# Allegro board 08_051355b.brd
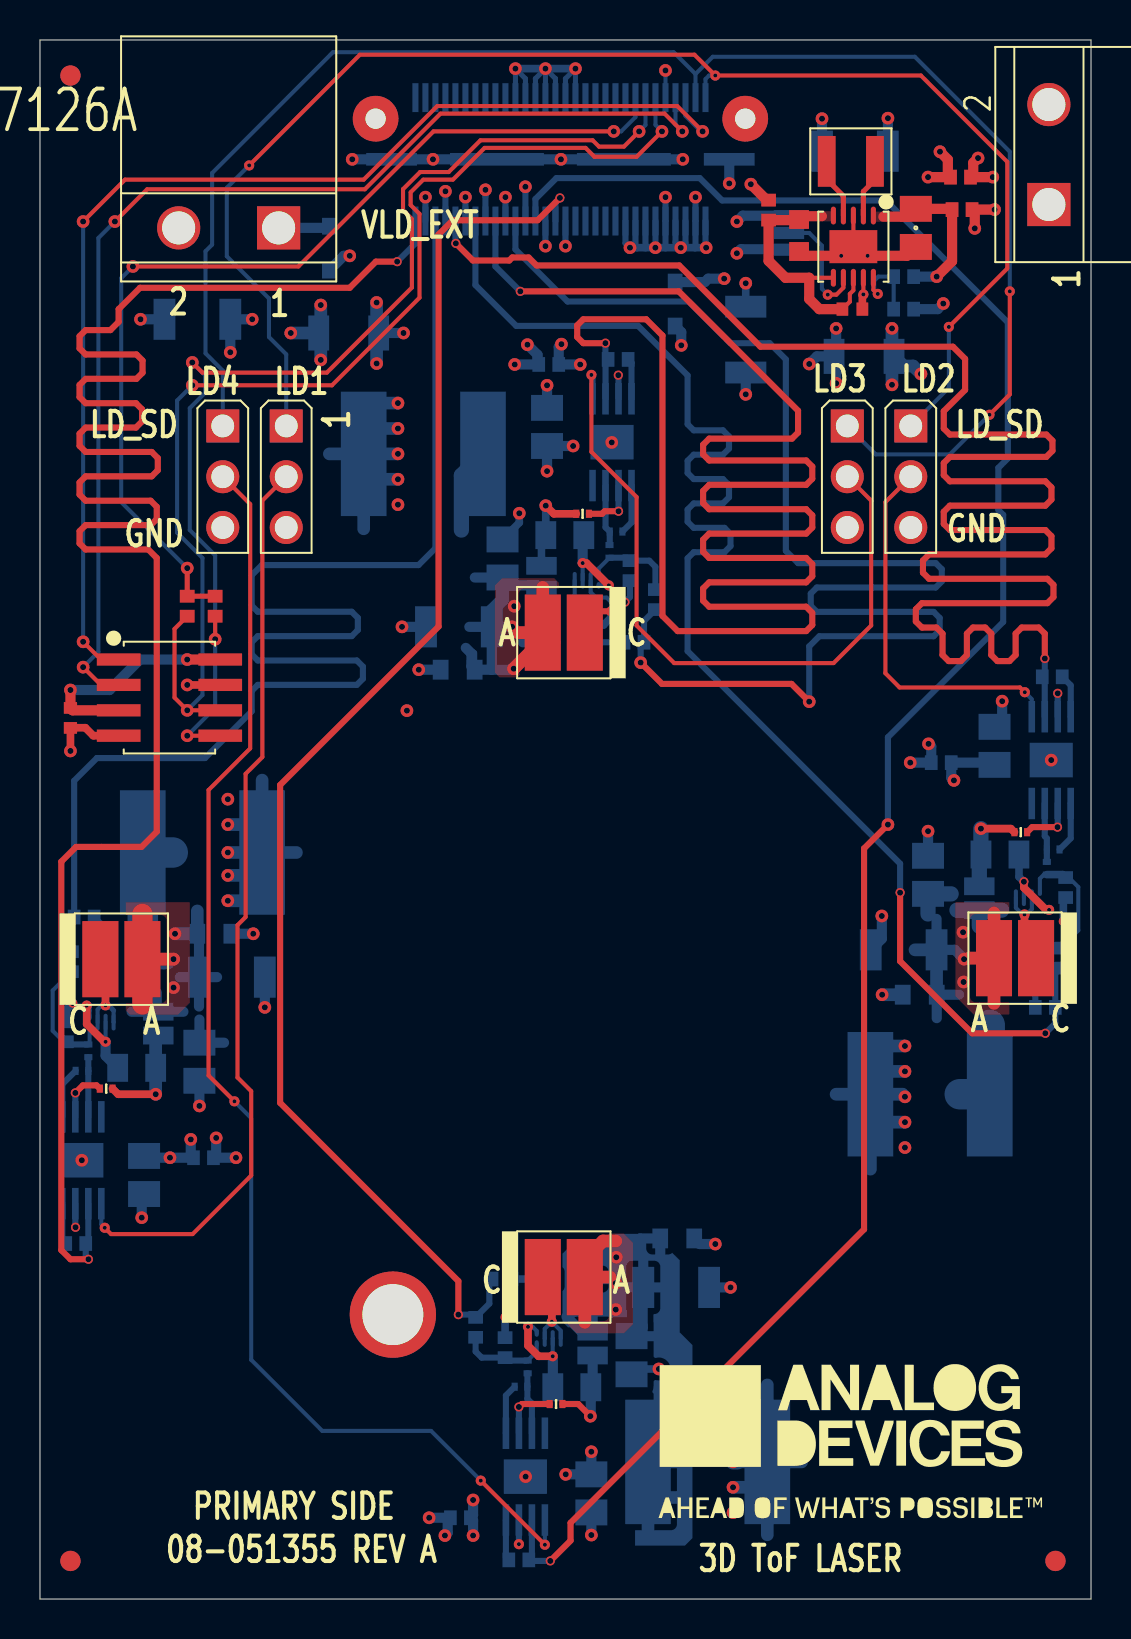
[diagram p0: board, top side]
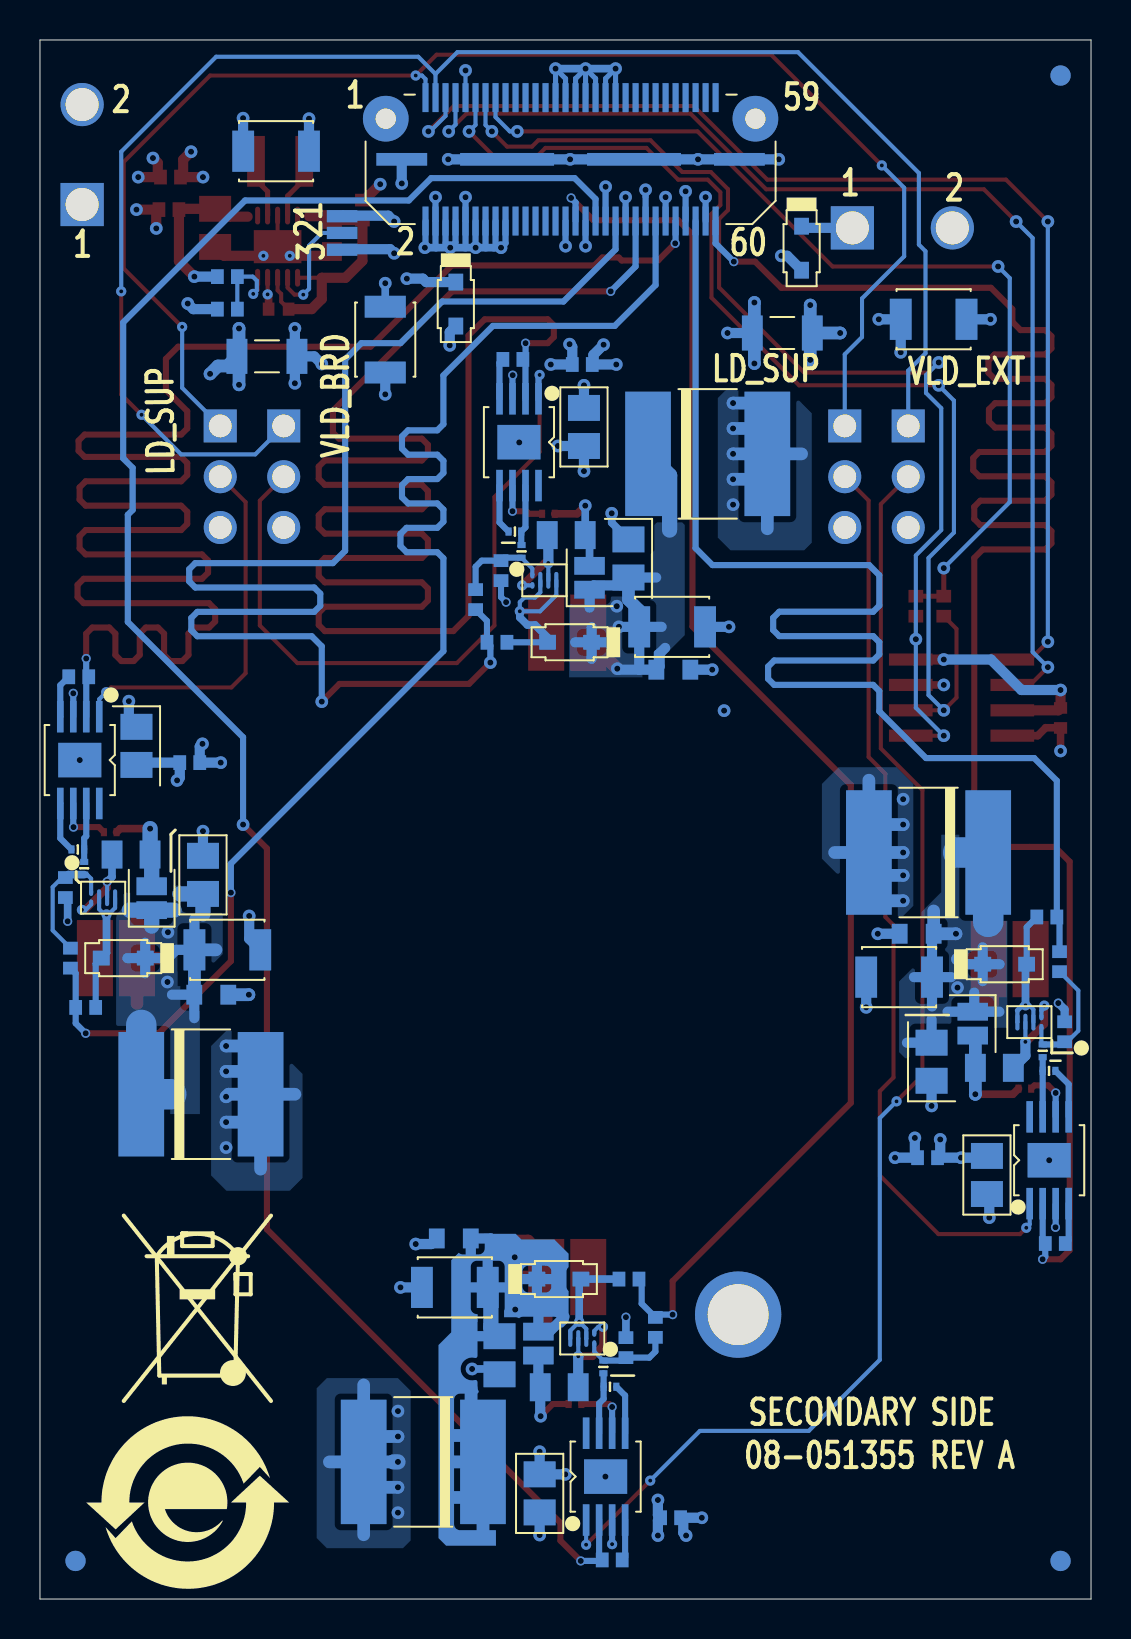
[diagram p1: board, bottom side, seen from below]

Outline 52.58 x 77.98 mm; copper layers: TOP, L2_GND, L3_PWR, L4_PWR, L5_GND, BOTTOM. Coordinates in mm from the lower left corner of the outline.
Outline path: 0,77.98 52.58,77.98 52.58,0 0,0 0,77.98

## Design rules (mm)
constraint set DEFAULT: min track width 0.203
net group TAL: nets TAL1 TAL2 TAL3 TAL4

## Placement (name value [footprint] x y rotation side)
C1  0.1uF  [C0201]  3.31 25.53 180 top
C2  0.1uF  [C0201]  25.82 9.75 180 top
C3  4.7UF  [C0805H53]  5.21 21.21 90 bottom
C4  4.7UF  [C0805H53]  27.58 5.28 90 bottom
C5  22NF  [C0306]  5.92 28.78 90 bottom
C6  22NF  [C0306]  27.65 12.78 90 bottom
C7  0.1uF  [C0201]  27.14 54.28 0 top
C8  0.1uF  [C0201]  49.06 38.35 0 top
C9  22UF  [C1210H106]  9.6 31.1 180 bottom
C10  22UF  [C1210H106]  31.83 15.59 180 bottom
C11  4.7UF  [C0805H53]  25.37 58.62 270 bottom
C12  4.7UF  [C0805H53]  47.75 42.67 270 bottom
C13  22UF  [C1210H106]  20.96 48.62 0 bottom
C14  22NF  [C0306]  25.09 51.08 270 bottom
C15  22UF  [C1210H106]  43.21 32.47 0 bottom
C16  22NF  [C0306]  46.99 35.05 270 bottom
C17  22UF  [C1210H106]  7.87 64.01 0 bottom
C18  22UF  [C1210H106]  35.31 62.99 90 bottom
C19  22UF  [C1210H106]  40.77 72.42 180 bottom
C20  470UF  [C7260]  8.13 37.34 0 bottom
C21  470UF  [C7260]  44.53 25.25 180 bottom
C22  470UF  [C7260]  33.4 6.86 0 bottom
C23  470UF  [C7260]  19.18 57.28 180 bottom
C24  10uF  [C0603]  37.97 68.2 90 top
C25  0.1UF  [C0402]  40.64 64.52 0 top
C26  22UF  [C0805H60]  43.81 68.58 90 top
C27  4.7UF  [C0805H53]  7.98 26.87 90 bottom
C28  4.7UF  [C0805H53]  44.42 36.22 270 bottom
C29  4.7UF  [C0805H53]  29.59 12.19 90 bottom
C30  4.7UF  [C0805H53]  23.14 52.04 270 bottom
C31  0.1UF  [C0402]  1.52 44.07 90 top
D5  PLZ13B-G3/H  [DO219AC]  4.32 31.75 180 bottom
D6  PLZ13B-G3/H  [DO219AC]  26.62 16 180 bottom
D7  PLZ13B-G3/H  [DO219AC]  14.48 67.56 270 bottom
D8  PLZ13B-G3/H  [DO219AC]  31.78 64.77 270 bottom
D9  PLZ13B-G3/H  [DO219AC]  26.09 47.85 0 bottom
D10  PLZ13B-G3/H  [DO219AC]  48.41 32.05 0 bottom
JP5  3PIN_SOLDER_JUMPER  [JPRSLD03]  37.47 68.33 270 bottom
L1  1.5UH  [L1008_A]  40.56 71.91 0 top
LD1  I940-G2332-NBC-D1-60B45R  [VCSEL2_3_5X3_5]  4.07 32 0 top
LD2  I940-G2332-NBC-D1-60B45R  [VCSEL2_3_5X3_5]  48.78 32.05 180 top
LD3  I940-G2332-NBC-D1-60B45R  [VCSEL2_3_5X3_5]  26.2 48.34 180 top
LD4  I940-G2332-NBC-D1-60B45R  [VCSEL2_3_5X3_5]  26.2 16.1 0 top
NOREF  -  []  -53.14 168.62 0 top
NOREF#2  -  [unnamed#2]  17.65 14.22 0 top
NOREF#3  -  []  1.52 1.91 0 top
NOREF#4  -  [unnamed#2]  50.8 1.91 0 top
NOREF#5  -  []  52.58 0 0 top
NOREF#6  -  []  1.52 1.91 0 top
NOREF#7  -  []  0 0 0 top
NOREF#8  -  [unnamed#2]  1.52 76.2 0 top
NOREF#9  -  []  52.58 0 90 top
NOREF#10  -  []  0 77.98 0 top
NOREF#11  -  [unnamed#2]  1.52 1.91 0 top
NOREF#12  -  []  40.56 7.87 0 top
NOREF#13  -  []  0 0 0 top
NOREF#14  -  []  -53.08 170.04 0 top
NOREF#15  -  []  52.58 0 90 top
NOREF#16  -  []  -34.29 -74.04 0 top
NOREF#17  -  []  0 77.98 270 top
NOREF#18  -  []  0 0 0 top
NOREF#19  -  []  -152.4 -254 0 top
NOREF#20  -  []  52.7 77.98 180 top
NOREF#21  -  []  26.57 98.68 0 top
NOREF#22  -  []  226.11 -117.6 0 top
NOREF#23  -  []  0 77.98 0 top
NOREF#24  -  []  119.38 127 0 top
NOREF#25  -  []  -57.86 157.56 0 top
NOREF#26  -  []  215.9 215.9 0 top
NOREF#27  -  []  -170.05 -267.97 0 top
NOREF#28  -  []  17.6 42.14 0 top
NOREF#29  -  []  45.19 4.83 180 bottom
NOREF#30  -  [unnamed#2]  1.52 76.2 180 bottom
NOREF#31  -  [unnamed#2]  1.52 1.91 180 bottom
NOREF#32  -  []  35.43 22.86 180 bottom
NOREF#33  -  [unnamed#2]  50.8 1.91 180 bottom
P1  QTH-030-04-L-D-A  [CNHDR2X30H630]  26.04 72.01 180 bottom
P2  Z5.530.3225.0  [CNWIELAND3225]  11.94 68.58 180 top
P3  22-03-2031  [CNMOLEX22-03-2031]  12.32 58.67 270 top
P4  22-03-2031  [CNMOLEX22-03-2031]  9.14 58.67 270 top
P5  22-03-2031  [CNMOLEX22-03-2031]  40.39 58.67 270 top
P6  22-03-2031  [CNMOLEX22-03-2031]  43.56 58.67 270 top
P7  Z5.530.3225.0  [CNWIELAND3225]  50.47 69.75 90 top
Q1  EPC2014C  [EPCX014X]  3.08 28.85 90 bottom
Q2  EPC2014C  [EPCX014X]  25.45 13.03 90 bottom
Q3  EPC2014C  [EPCX014X]  27.35 50.95 270 bottom
Q4  EPC2014C  [EPCX014X]  49.42 35.08 270 bottom
R1  0  [R0402]  1.79 17.78 180 bottom
R2  0  [R0402]  23.95 1.96 180 bottom
R3  0.33  [R0805]  4.84 26.57 180 bottom
R4  0.33  [R0805]  26.6 10.59 180 bottom
R5  0  [R0603]  8.72 33.27 180 bottom
R6  0  [R0603]  31.88 18.03 180 bottom
R7  4.7  [R0201]  2.42 27.42 90 bottom
R8  4.7  [R0201]  24.39 11.61 90 bottom
R9  0  [R0402]  28.92 62 0 bottom
R10  0  [R0402]  50.64 46.13 0 bottom
R11  0  [R0603]  20.9 46.48 0 bottom
R12  4.7  [R0201]  28.49 52.4 270 bottom
R13  0  [R0603]  44.01 30.23 0 bottom
R14  4.7  [R0201]  50.37 36.55 270 bottom
R15  0.33  [R0805]  26.25 53.21 0 bottom
R16  0.33  [R0805]  48.02 37.24 0 bottom
R17  10K  [R0402]  1.32 28.37 90 bottom
R18  10K  [R0402]  23.27 12.57 90 bottom
R19  10K  [R0402]  29.51 51.44 270 bottom
R20  10K  [R0402]  51.31 35.59 270 bottom
R21  0  [R1206]  15.44 63.32 0 bottom
R22  0  [R1206]  41.22 62.15 0 bottom
R23  50  [R0402]  1.57 31.88 90 bottom
R24  50  [R0402]  51.05 32.05 270 bottom
R25  50  [R0402]  2.21 34.11 180 bottom
R26  50  [R0402]  50.29 29.59 0 bottom
R27  50  [R0402]  21.79 13.59 90 bottom
R28  50  [R0402]  30.78 49.99 270 bottom
R29  50  [R0402]  23.11 16 180 bottom
R30  50  [R0402]  29.72 47.85 0 bottom
R31  0  [R0402]  8.18 22.07 180 bottom
R32  0  [R0402]  45.09 41.83 0 bottom
R33  0  [R0402]  21.03 4.06 0 bottom
R34  0  [R0402]  25.45 61.75 0 bottom
R35  0  [R0402]  43.21 64.52 180 bottom
R36  0  [R0402]  36.45 69.47 90 top
R37  0  [R0402]  43.21 66.14 0 bottom
R38  0  [R0402]  46.05 71.12 180 top
R39  0  [R0402]  46.13 69.49 0 top
R40  10K  [R0402]  8.76 49.66 270 top
R41  10K  [R0402]  7.37 49.66 270 top
R42  0  [R0201]  2.1 26.42 0 bottom
R43  0  [R0201]  50.69 37.49 180 bottom
R44  0  [R0201]  24.06 10.62 0 bottom
R45  0  [R0201]  28.82 53.39 180 bottom
U1  ADP3624ARHZ  [MSOP8_PAD2_16X1_73]  2.09 21.95 180 bottom
U2  ADP3624ARHZ  [MSOP8_PAD2_16X1_73]  24.28 6.12 180 bottom
U3  ADP3624ARHZ  [MSOP8_PAD2_16X1_73]  28.62 57.86 0 bottom
U4  ADP3624ARHZ  [MSOP8_PAD2_16X1_73]  50.59 41.96 0 bottom
U5  ADP2504ACPZ-5.0  [DFN10_3X3_PAD2_38X1_64]  40.69 67.64 180 top
U6  ADT7410TRZ  [SO8]  6.48 45.09 270 top

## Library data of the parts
C1 C2 C7 C8 = CAP: Tolerance: 20; User Part Number: UPN; alternate symbols: (); part number: CAP_SM-0.1UF,16V,20,E017331,C0201; tolerance: 20
C3 C4 C11 C12 C27-C30 = CAP: Tolerance: 10; User Part Number: UPN; alternate symbols: (); part number: CAP_SM-4.7UF,25V,10,E025752,C0805H53; tolerance: 10
C5 C6 C14 C16 = CAP: Tolerance: 20; User Part Number: UPN; alternate symbols: (); part number: CAP_SM-22NF,16V,20,E034159,C0306; tolerance: 20
C9 C10 C13 C15 C17-C19 = CAP: Tolerance: 10; User Part Number: UPN; alternate symbols: (); part number: CAP_SM-22UF,25V,10,E025745,C1210H106; tolerance: 10
C20-C23 = CAPP: Tolerance: 10; User Part Number: UPN; alternate symbols: (); part number: CAPP_SM-470UF,10V,10,E027243,C7260; tolerance: 10
C24 = CAP: User Part Number: UPN; Tolerance: 20; alternate symbols: (); part number: CAP_SM-10UF,6.3V,20,E007143,C0603; tolerance: 20
C25 C31 = CAP: User Part Number: UPN; Tolerance: 10; alternate symbols: (); part number: CAP_SM-0.1UF,16V,10,E027519,C0402; tolerance: 10
C26 = CAP: Tolerance: 20; User Part Number: UPN; alternate symbols: (); part number: CAP_SM-22UF,10V,20,E032369,C0805H60; tolerance: 20
D5-D10 = DIOZNR: User Part Number: UPN; Tolerance: 2; alternate symbols: (); part number: DIOZNR_SM-PLZ13B-G3/H,13V,2,E025186,DO219AC; tolerance: 2
JP5 = NC3P_JMPR: Tolerance: N/A; User Part Number: UPN; alternate symbols: (); part number: NC3P_JMPR_SM-3PIN_SOLDER_JUMPER,E005606,JPRSLD03; tolerance: N/A
L1 = IND: Tolerance: 20; User Part Number: UPN; alternate symbols: (); part number: IND_SM-1.5UH,20,E026128,L1008_A; tolerance: 20
LD1-LD4 = DIOLASER: User Part Number: UPN; Tolerance: N/A; alternate symbols: (); part number: DIOLASER_SM-I940-G2332-NBC-D1-60B45R,5V,N/A,E034255,VCSEL2_3_5X3_5; tolerance: N/A
P1 = CN60P_ODD_EVEN_4GND: User Part Number: UPN; Tolerance: N/A; alternate symbols: (); part number: CN60P_ODD_EVEN_4GND_SM-QTH-030-04-L-D-A,E023035,CNHDR2X30H630; tolerance: N/A
P2 P7 = CN2P: User Part Number: UPN; Tolerance: N/A; alternate symbols: (); part number: CN2P_TH-Z5.530.3225.0,E008161,CNWIELAND3225; tolerance: N/A
P3-P6 = CN3P: User Part Number: UPN; Tolerance: N/A; alternate symbols: (); part number: CN3P_TH-22-03-2031,E005626,CNMOLEX22-03-2031; tolerance: N/A
Q1-Q4 = TRANNGANFET: Tolerance: N/A; User Part Number: UPN; alternate symbols: (); part number: TRANNGANFET_SM-EPC2014C,E023055,EPCX014X; tolerance: N/A
R1 R2 R9 R10 R31-R39 = RES: User Part Number: UPN; Tolerance: 5; alternate symbols: (R0402L,R0402L_ALT); part number: RES_SM-0,E003438,N/A,5,R0402; tolerance: 5
R3 R4 R15 R16 = RES: User Part Number: UPN; Tolerance: 1; alternate symbols: (R0805L); part number: RES_SM-0.33,E013321,1/8W,1,R0805; tolerance: 1
R5 R6 R11 R13 = RES: User Part Number: UPN; Tolerance: 5; alternate symbols: (R0603L); part number: RES_SM-0,E006826,1/10W,5,R0603; tolerance: 5
R7 R8 R12 R14 = RES: Tolerance: 5; User Part Number: UPN; alternate symbols: (); part number: RES_SM-4.7,E019116,1/20W,5,R0201; tolerance: 5
R17-R20 = RES: User Part Number: UPN; Tolerance: 1; alternate symbols: (R0402L,R0402L_ALT); part number: RES_SM-10K,E003751,1/10W,1,R0402; tolerance: 1
R21 R22 = RES: User Part Number: UPN; Tolerance: N/A; alternate symbols: (); part number: RES_SM-0,E014206,1/2W,N/A,R1206; tolerance: N/A
R23-R30 = RES: User Part Number: UPN; Tolerance: 0.1; alternate symbols: (R0402L); part number: RES_SM-50,E016309,1/20W,0.1,R0402; tolerance: 0.1
R40 R41 = RES: User Part Number: UPN; Tolerance: 5; alternate symbols: (R0402L); part number: RES_SM-10K,E017176,1/10W,5,R0402; tolerance: 5
R42-R45 = RES: Tolerance: N/A; User Part Number: UPN; alternate symbols: (); part number: RES_SM-0,E004015,1/20W,0,R0201; tolerance: N/A
U1-U4 = ADP36X4: Tolerance: N/A; User Part Number: UPN; alternate symbols: (); part number: ADP36X4_SM-ADP3624ARHZ,E025682,MSOP8_PAD2_16X1_73; tolerance: N/A
U5 = ADP250X: Tolerance: N/A; User Part Number: UPN; alternate symbols: (); part number: ADP250X_SM-ADP2504ACPZ-5.0,E033974,DFN10_3X3_PAD2_38X1_64; tolerance: N/A
U6 = ADT7410: Tolerance: N/A; User Part Number: UPN; alternate symbols: (); part number: ADT7410_SM-ADT7410TRZ,E010871,SO8; tolerance: N/A

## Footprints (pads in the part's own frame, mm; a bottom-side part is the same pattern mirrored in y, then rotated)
C0201
  rect 0.305x0.406 smd: 1(-0.318,0) 2(0.318,0)
C0306
  rect 0.889x1.524 smd: 1(-0.597,0) 2(0.597,0)
C0402
  rect 0.584x0.66 smd: 1(-0.5,0) 2(0.5,0)
C0603
  rect 0.94x0.991 smd: 1(-0.8,0) 2(0.8,0)
C0805H53
  rect 1.295x1.6 smd: 1(-0.953,0) 2(0.953,0)
C0805H60
  rect 1.295x1.6 smd: 1(-0.953,0) 2(0.953,0)
C1210H106
  rect 1.092x2.057 smd: 1(-1.646,0) 2(1.646,0)
C7260
  rect 2.286x6.223 smd: N(2.985,0) P(-2.985,0)
CNHDR2X30H630
  round 2.286 hole 1.016 unplated: (-9.246,2.032) (9.246,2.032)
  rect 0.305x1.448 smd: 1(-7.257,3.086) 2(-7.257,-3.086) 3(-6.756,3.086) 4(-6.756,-3.086) 5(-6.256,3.086) 6(-6.256,-3.086) 7(-5.756,3.086) 8(-5.756,-3.086) 9(-5.255,3.086) 10(-5.255,-3.086) 11(-4.755,3.086) 12(-4.755,-3.086) 13(-4.255,3.086) 14(-4.255,-3.086) 15(-3.754,3.086) 16(-3.754,-3.086) 17(-3.254,3.086) 18(-3.254,-3.086) 19(-2.753,3.086) 20(-2.753,-3.086) 21(-2.253,3.086) 22(-2.253,-3.086) 23(-1.753,3.086) 24(-1.753,-3.086) 25(-1.252,3.086) 26(-1.252,-3.086) 27(-0.752,3.086) 28(-0.752,-3.086) 29(-0.251,3.086) 30(-0.251,-3.086) 31(0.249,3.086) 32(0.249,-3.086) 33(0.749,3.086) 34(0.749,-3.086) 35(1.25,3.086) 36(1.25,-3.086) 37(1.75,3.086) 38(1.75,-3.086) 39(2.25,3.086) 40(2.25,-3.086) 41(2.751,3.086) 42(2.751,-3.086) 43(3.251,3.086) 44(3.251,-3.086) 45(3.752,3.086) 46(3.752,-3.086) 47(4.252,3.086) 48(4.252,-3.086) 49(4.752,3.086) 50(4.752,-3.086) 51(5.253,3.086) 52(5.253,-3.086) 53(5.753,3.086) 54(5.753,-3.086) 55(6.253,3.086) 56(6.253,-3.086) 57(6.754,3.086) 58(6.754,-3.086) 59(7.254,3.086) 60(7.254,-3.086)
  rect 2.54x0.635 smd: PAD1(-8.445,0) PAD4(8.445,0)
  rect 4.699x0.635 smd: PAD2(-3.175,0) PAD3(3.175,0)
CNMOLEX22-03-2031
  rect 1.651x1.651 hole 1.143: 1(0,0)
  round 1.651 hole 1.143: 2(2.54,0) 3(5.08,0)
CNWIELAND3225
  rect 2.159x2.159 hole 1.651: 1(0,0)
  round 2.159 hole 1.651: 2(5,0)
DFN10_3X3_PAD2_38X1_64
  oval 0.254x0.889 smd: 1(-1,-1.555) 2(-0.5,-1.555) 3(0,-1.555) 4(0.5,-1.555) 5(1,-1.555) 6(1,1.555) 7(0.5,1.555) 8(0,1.555) 9(-0.5,1.555) 10(-1,1.555)
  rect 2.388x1.651 smd: PAD(0,0)
DO219AC
  rect 0.838x0.737 smd: A(1.1,0) C(-1.1,0)
EPCX014X
  oval 0.33x0.203 smd: 1(-0.253,-0.601) 2(0.253,-0.601)
  oval 0.838x0.203 smd: 3(0,-0.201) 4(0,0.199) 5(0,0.599)
JPRSLD03
  rect 0.61x1.524 smd: 1(-0.838,0) 2(0,0) 3(0.838,0)
L1008_A
  rect 0.889x2.54 smd: 1(-1.206,0) 2(1.206,0)
MSOP8_PAD2_16X1_73
  rect 0.33x1.575 smd: 1(-0.975,-2.171) 2(-0.325,-2.171) 3(0.325,-2.171) 4(0.975,-2.171) 5(0.975,2.171) 6(0.325,2.171) 7(-0.325,2.171) 8(-0.975,2.171)
  rect 2.159x1.727 smd: PAD(0,0)
R0201
  rect 0.305x0.406 smd: 1(-0.318,0) 2(0.318,0)
R0402
  rect 0.635x0.737 smd: 1(-0.5,0) 2(0.5,0)
R0603
  rect 0.787x0.991 smd: 1(-0.85,0) 2(0.85,0)
R0805
  rect 1.041x1.397 smd: 1(-0.95,0) 2(0.95,0)
R1206
  rect 1.041x1.753 smd: 1(-1.5,0) 2(1.5,0)
SO8
  rect 0.61x2.184 smd: 1(-1.905,-2.54) 2(-0.635,-2.54) 3(0.635,-2.54) 4(1.905,-2.54) 5(1.905,2.54) 6(0.635,2.54) 7(-0.635,2.54) 8(-1.905,2.54)
unnamed#2
  round 4.318 hole 3.048 unplated: (0,0)
VCSEL2_3_5X3_5
  rect 1.803x3.81 smd: A(1.052,0) C(-1.052,0)

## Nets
5V_LD: R31.1 R32.1 R33.1 R34.1 R38.1 R39.2(N2)
5VDD_CON: C19.2(N2) JP5.1 P1.27 P1.29 P1.31 P1.33 P1.35 P1.37 P1.39 R36.2(N2) R38.2(N2)
AGND: C1.1 C2.1 C3.1 C4.1 C5.1 C6.1 C7.1 C8.1 C9.1 C10.1 C11.1 C12.1 C13.1 C14.1 C15.1 C16.1 C17.1 C18.1 C19.1 C20.N(N2) C21.N(N2) C22.N(N2) C23.N(N2) C24.1 C25.2(N2) C26.1 C27.1 C28.1 C29.1 C30.1 C31.1 D7.A(P) D8.A(P) JP5.3 P1.30 P1.34 P1.38 P1.42 P1.46 P1.50 P1.54 P1.58 P1.PAD1 P1.PAD2 P1.PAD3 P1.PAD4 P2.2(N2) P3.3(N3) P4.3(N3) P5.3(N3) P6.3(N3) R3.1 R4.1 R15.1 R16.1 R17.2(N2) R18.2(N2) R19.2(N2) R20.2(N2) R35.1 U1.3 U1.PAD U2.3 U2.PAD U3.3 U3.PAD U4.3 U4.PAD U5.3 U5.9 U5.PAD U6.4 U6.7
3P3VDD: C31.2(N2) P1.9 U6.3 U6.8(VDD)
CT_LASER: P1.11 R41.2(N2) U6.6
DS1: C5.2(N2) C9.2(N2) C20.P C27.2(N2) D5.C LD1.A R5.2(N2)
DS2: C15.2(N2) C16.2(N2) C21.P C28.2(N2) D10.C LD2.A R13.2(N2)
DS3: C13.2(N2) C14.2(N2) C23.P C30.2(N2) D9.C LD3.A R11.2(N2)
DS4: C6.2(N2) C10.2(N2) C22.P C29.2(N2) D6.C LD4.A R6.2(N2)
I2C0_SCL: P1.5 U6.1
I2C0_SDA: P1.7 U6.2
INT_LASER: P1.13 R40.2(N2) U6.5
IOVDD: P1.15 R40.1 R41.1
LD1: P1.60 R1.1 U1.2
LD2: P1.52 R10.1 U4.2
LD3: P1.44 R9.1 U3.2
LD4: P1.36 R2.1 U2.2
LD_SD1: P1.1 P3.1 P6.1
LD_SD2: P1.3 P4.1 P5.1
LD_SUPPLY: R5.1 R6.1 R11.1 R13.1 R21.2(N2) R22.2(N2)
SYNC: JP5.2(COM) U5.7
TAL1: P1.56 R23.2(N2) R25.2(N2)
TAL2: P1.48 R24.2(N2) R26.2(N2)
TAL3: P1.40 R28.2(N2) R30.2(N2)
TAL4: P1.32 R27.2(N2) R29.2(N2)
UNNAMED_4_ADP36X4_I6_INB: R1.2(N2) U1.4
UNNAMED_4_ADP36X4_I6_OUTA: R7.1 R42.2(N2) U1.7
UNNAMED_4_ADP36X4_I6_OUTB: R42.1 U1.5
UNNAMED_4_ADP36X4_I6_SD: P3.2 U1.1
UNNAMED_4_ADP36X4_I6_VDD: C1.2(N2) C3.2(N2) R31.2(N2) U1.6(VDD)
UNNAMED_4_ADP36X4_I26_INB: R2.2(N2) U2.4
UNNAMED_4_ADP36X4_I26_OUTA: R8.1 R44.2(N2) U2.7
UNNAMED_4_ADP36X4_I26_OUTB: R44.1 U2.5
UNNAMED_4_ADP36X4_I26_SD: P4.2 U2.1
UNNAMED_4_ADP36X4_I26_VDD: C2.2(N2) C4.2(N2) R33.2(N2) U2.6(VDD)
UNNAMED_4_ADP36X4_I59_INB: R9.2(N2) U3.4
UNNAMED_4_ADP36X4_I59_OUTA: R12.1 R45.2(N2) U3.7
UNNAMED_4_ADP36X4_I59_OUTB: R45.1 U3.5
UNNAMED_4_ADP36X4_I59_SD: P5.2 U3.1
UNNAMED_4_ADP36X4_I59_VDD: C7.2(N2) C11.2(N2) R34.2(N2) U3.6(VDD)
UNNAMED_4_ADP36X4_I77_INB: R10.2(N2) U4.4
UNNAMED_4_ADP36X4_I77_OUTA: R14.1 R43.2(N2) U4.7
UNNAMED_4_ADP36X4_I77_OUTB: R43.1 U4.5
UNNAMED_4_ADP36X4_I77_SD: P6.2 U4.1
UNNAMED_4_ADP36X4_I77_VDD: C8.2(N2) C12.2(N2) R32.2(N2) U4.6(VDD)
UNNAMED_4_ADP250X_I213_EN: C24.2(N2) C25.1 R36.1 U5.5 U5.6 U5.8
UNNAMED_4_ADP250X_I213_FB: R35.2(N2) R37.1 U5.10
UNNAMED_4_ADP250X_I213_SW1: L1.1 U5.4
UNNAMED_4_ADP250X_I213_SW2: L1.2(N2) U5.2
UNNAMED_4_ADP250X_I213_VOUT: C26.2(N2) R37.2(N2) R39.1 U5.1(VOUT)
UNNAMED_4_CAP_I140_N2: C18.2(N2) D8.C P7.1 R22.1
UNNAMED_4_DIOZNR_I124_P: D5.A(P) LD1.C Q1.3 Q1.5 R25.1
UNNAMED_4_DIOZNR_I125_P: D6.A(P) LD4.C Q2.3 Q2.5 R29.1
UNNAMED_4_DIOZNR_I126_P: D10.A(P) LD2.C Q4.3 Q4.5 R26.1
UNNAMED_4_DIOZNR_I127_P: D9.A(P) LD3.C Q3.3 Q3.5 R30.1
UNNAMED_4_RES_I11_N2: Q1.1 R7.2(N2) R17.1 R23.1
UNNAMED_4_RES_I53_N2: Q1.2(SUBSTRATE) Q1.4 R3.2(N2)
UNNAMED_4_RES_I54_N2: Q2.2(SUBSTRATE) Q2.4 R4.2(N2)
UNNAMED_4_RES_I70_N2: Q3.2(SUBSTRATE) Q3.4 R15.2(N2)
UNNAMED_4_RES_I87_N2: Q4.2(SUBSTRATE) Q4.4 R16.2(N2)
UNNAMED_4_RES_I116_N1: Q3.1 R12.2(N2) R19.1 R28.1
UNNAMED_4_RES_I118_N1: Q4.1 R14.2(N2) R20.1 R24.1
UNNAMED_4_RES_I120_N1: Q2.1 R8.2(N2) R18.1 R27.1
VLD_BRD: P1.2 P1.4 P1.6 P1.8 P1.10 P1.12 P1.14 P1.16 P1.18(N9) P7.2(N2)
VLD_EXT: C17.2(N2) D7.C P2.1 R21.1

Pads without a net: P1 17 19 20 21 22 23 24 25 26 28 41 43 45 47 49 51 53 55 57 59; U1 8; U2 8; U3 8; U4 8

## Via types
v1: diameter 0.635, hole 0.305, TOP to BOTTOM, 155 vias
v2: diameter 0.508, hole 0.203, TOP to BOTTOM, 28 vias
v3: diameter 0.457, hole 0.305, TOP to BOTTOM, 23 vias

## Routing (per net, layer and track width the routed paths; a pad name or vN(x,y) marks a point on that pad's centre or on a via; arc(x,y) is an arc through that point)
5V_LD: length 13.1
  TOP w0.508: v1(46.76,68.55) 46.76,69.36 R39.2 v1(47.75,69.49) ; v1(47.66,71.12) R38.1 46.69,71.26 46.69,71.83 v1(46.93,72.07)
  BOTTOM w0.508: v1(23.75,61.75) R34.1 24.89,61.81 24.89,62.23 v1(24.38,62.74) ; v1(8.81,23.06) 8.81,22.21 R31.1 v1(9.8,22.07) ; v1(19.47,4.06) R33.1 20.4,3.93 20.4,3.31 v1(20.26,3.17) ; v1(44.45,42.77) 44.59,42.64 R32.1 v1(43.54,41.83)
5VDD_CON: length 22.2
  TOP w0.508: v1(44.42,71.12) R38.2 45.42,71.26 45.42,72 v1(45.02,72.39) ; R36.2 36.36,69.97 v1(35.56,70.76)
  BOTTOM w0.254: P1.35 24.79,76.04 v1(25.29,76.55) ; P1.29 26.29,76.05 v1(26.79,76.55) P1.27 ; v1(25.29,76.55) P1.33 ; v1(25.29,76.55) 25.79,76.04 P1.31 ; P1.39 v1(23.78,76.55) 24.28,76.05 P1.37
  BOTTOM w0.381: v1(26.79,76.55) v1(25.29,76.55) v1(23.78,76.55)
  BOTTOM w0.508: v1(34.86,68.9) 35.15,69.19 37.44,69.19 JP5.1 ; C19.2 v1(39.12,74.04)
AGND: length 157
  TOP w0.203: U5.3 U5.PAD ; U5.9 v2(41.19,65.25)
  TOP w0.305: v1(27.53,9.14) 26.92,9.75 C2.1
  TOP w0.381: C8.1 48.57,38.53 v1(47.07,38.53) ; C7.1 25.71,54.28 v1(25.3,54.69) ; C25.2 41.14,65.2 v2(41.19,65.25) ; C1.1 3.91,25.25 v1(5.79,25.25) ; U6.7 v1(7.37,45.72) ; 3.94,43.18 2.67,43.18 2.27,43.58 1.52,43.58 C31.1 v1(1.52,42.42)
  TOP w0.508: v2(40.08,67.18) 38.19,67.18 C24.1 ; C26.1 43.37,67.18 v2(41.4,67.18)
  BOTTOM w0.305: v3(29.26,49.86) 29.51,50.11 R19.2 ; P1.54 v1(20.28,70.41) ; U2.3 v2(23.96,2.74) ; P1.38 24.28,70.63 v1(24.28,70.64) ; U3.3 28.94,61.2 v3(28.93,61.21) ; v1(22.28,70.48) 22.28,70.14 P1.46 ; U1.3 1.77,18.6 v3(1.78,18.59) ; P1.50 v1(21.28,70.12) ; v1(19.28,70.12) P1.58 ; U4.3 v3(50.91,45.3) ; v1(23.28,70.12) P1.42 ; P1.34 v1(25.29,67.67) ; P1.30 v1(26.29,67.67)
  BOTTOM w0.381: C14.1 25.09,52.99 R15.1 25.3,53.22 v1(25.3,54.69) ; C29.1 29.86,11.51 v1(30.96,11.51) ; v1(23.98,54.31) 23.98,53.84 C30.1 ; R20.2 51.19,34.97 v3(51.19,33.9) ; R18.2 v3(23.27,14.1)
  BOTTOM w0.406: v3(1.64,29.81) 1.32,29.49 R17.2
  BOTTOM w0.508: R35.1 44.91,64.52 v1(45.19,64.8) ; v1(42.11,34.16) 42.11,33.02 C15.1 ; C12.1 48.13,44.01 v1(48.13,44.91) ; C18.1 v1(35.31,60.25) ; v1(32.08,62.7) 32.08,63.37 D8.A ; v1(32.16,72.01) P1.PAD2 v1(26.06,72.01) P1.PAD3 v1(19.66,72.01) P1.PAD4 v1(15.62,72.01) ; C28.1 v1(44.42,38.4) ; C4.1 v1(27.58,3.2) ; v1(25.37,60.71) C11.1 ; v1(15.49,67.18) 15.2,67.18 D7.A ; C10.1 v1(34.54,15.59) ; C13.1 v1(18.11,48.62) ; C6.1 27.65,10.68 R4.1 27.55,9.16 v1(27.53,9.14) ; v1(34.86,67.31) 35.06,67.51 37.44,67.51 JP5.3 ; C3.1 5.21,20.07 5.09,19.95 v1(5.09,19.08) ; C19.1 42.42,72.42 v1(42.42,74.07) ; C27.1 v1(7.98,24.66) ; C9.1 v1(11.25,29.59) ; C17.1 v1(5.03,64.01) ; P1.PAD1 v1(34.48,70.8)
  BOTTOM w0.635: C5.1 5.79,28.05 R3.1 5.79,25.25 v1(5.79,25.25) ; C22.N 36.39,6.1 ; C22.N 34.89,6.86 ; C22.N 38.1,6.86 ; C22.N 36.39,7.62 ; 36.39,6.1 36.39,3.21 ; 36.39,6.1 35.88,5.59 v1(34.67,5.59) ; C21.N 41.54,24.36 ; C21.N 43.14,25.25 v1(43.27,25.12) ; C21.N 39.83,25.25 ; C21.N 41.54,25.88 ; 41.54,24.36 42.05,23.85 v1(43.27,23.85) ; 41.54,24.36 41.54,21.5 ; v1(43.27,26.39) 42.05,26.39 41.54,25.88 ; 12.83,37.34 C20.N ; C20.N 11.11,36.7 ; C20.N v1(9.4,37.34) ; C20.N 11.11,38.23 ; v1(9.4,34.93) 10.6,34.93 11.11,35.43 11.11,36.7 ; v1(17.91,58.55) 16.7,58.55 16.19,58.04 ; 11.11,38.23 11.11,40.96 ; 11.11,38.23 10.6,38.73 v1(9.4,38.73) ; C23.N 16.19,56.52 ; C23.N v1(17.91,57.28) ; C23.N 16.19,58.04 ; C23.N 14.48,57.28 ; 16.19,56.52 16.19,53.53 ; 16.19,56.52 16.7,56.01 v1(17.91,56.01) ; 11.11,36.7 10.6,36.2 v1(9.4,36.2) ; 36.39,7.62 35.88,8.13 v1(34.67,8.13) ; 36.39,7.62 36.39,10.71 ; v1(43.27,27.66) 42.11,27.66 41.54,27.09 41.54,25.88 ; 16.19,58.04 16.19,59.31 16.7,59.82 v1(17.91,59.82)
  BOTTOM w0.762: C16.1 46.99,37.15 R16.1 47.07,37.24 v1(47.07,38.53) ; 34.89,6.86 v1(34.67,6.86)
  vias: v1(2.09,21.95) v1(9.4,40.01) v1(17.91,54.74) v1(18.36,44.43) v1(24.29,6.12) v1(28.6,57.85) v1(34.67,9.4) v1(34.67,4.32) v1(43.27,22.58) v1(50.59,41.96)
3P3VDD: length 12.8
  TOP w0.508: U6.8 v1(7.37,46.99) ; 3.94,44.45 1.63,44.45 1.52,44.56 C31.2 v1(1.52,45.47)
  BOTTOM w0.203: P1.9 v1(31.29,76.45)
  BOTTOM w0.508: v1(1.52,45.47) 3.48,45.47 5,46.99 v1(7.37,46.99)
CT_LASER: length 59
  TOP w0.203: v1(7.62,60.71) 14.61,60.71 18.99,65.09 18.99,69.28 18.54,69.72 18.54,70.36 19.18,70.99 20.65,70.99 22.24,72.58 27.29,72.58 27.74,72.14 29.85,72.14 v1(31.12,73.41) ; U6.6 v1(7.37,44.45) 6.73,45.09 6.73,48.52 R41.2
  BOTTOM w0.203: v1(7.37,44.45) 8.13,45.21 8.13,52.07 6.86,53.34 6.86,59.94 v1(7.62,60.71) ; v1(31.12,73.41) 30.79,73.73 P1.11
DS1: length 30.5
  TOP w0.635: LD1.A v1(6.68,32)
  TOP w1.016: 5.12,29.74 LD1.A 5.12,34.26
  BOTTOM w0.254: R5.2 7.87,34.12 ; C5.2 5.92,30.18
  BOTTOM w0.508: C5.2 7.18,29.38 ; C5.2 4.58,29.38 ; C5.2 5.84,29.45 5.84,30.33 ; C9.2 8.86,31.1 ; C9.2 7.96,33.19 ; C9.2 7.96,29.64 ; C9.2 7,31.1 ; v1(6.68,32) 6.43,31.75 D5.C ; 9.21,27.83 C27.2 7.98,28.98 ; 7.96,33.19 R5.2 7.96,33.19 ; 5.42,30.9 D5.C ; D5.C 5.42,32.6 ; D5.C 4.57,31.75
  BOTTOM w0.635: v1(6.76,33.27) R5.2 7.87,34.41
  BOTTOM w1.524: 5.14,33.87 C20.P 6.64,37.34
  vias: v1(6.68,30.58)
DS2: length 29.1
  TOP w0.635: 46.47,32.05 LD2.A ; LD2.A 47.73,29.79 ; LD2.A 47.73,34.32
  BOTTOM w0.254: 44.86,29.38 R13.2
  BOTTOM w0.508: 45.97,30.23 R13.2 44.86,29.05 ; 44.85,34.02 C15.2 45.76,32.47 v1(46.23,32) 46.28,32.05 D10.C ; 47.31,31.3 D10.C ; D10.C 48.21,32.05 ; D10.C 47.31,32.82
  BOTTOM w0.635: 43.77,32.47 C15.2 44.85,30.23 R13.2
  BOTTOM w0.762: C16.2 48.11,34.46 ; C16.2 45.87,34.46 ; C16.2 46.99,33.65 ; 44.42,34.26 C28.2 45.58,35.27 ; R13.2 44.85,30.23
  BOTTOM w1.524: 47.51,28.71 C21.P 46.01,25.25
  vias: v1(46.18,33.35) v1(46.2,30.86)
DS3: length 29
  TOP w0.635: LD3.A 25.15,47.99 v1(23.7,46.53) ; LD3.A 25.15,50.6 ; LD3.A 23.9,48.34
  BOTTOM w0.254: R11.2 21.75,47.33
  BOTTOM w0.508: 22.6,46.48 R11.2 21.58,46.64 21.58,47.29 21.3,47.57 ; 22.6,46.48 22.6,46.49 C13.2 ; 22.6,46.48 23.65,46.48 v1(23.7,46.53) ; C13.2 v1(23.62,48.62) ; C13.2 21.48,48.62 ; 21.76,51.09 C30.2 23.53,50.7 24.87,50.7 C14.2 25.09,49.59 ; 24.16,47.85 D9.C ; D9.C 25.81,47.85 ; D9.C 24.99,47.02 ; D9.C 24.99,48.61
  BOTTOM w0.635: C13.2 22.6,49.45 23.14,49.99 C30.2
  BOTTOM w0.762: C23.P 21.08,56.2 21.08,53.47
  vias: v1(23.72,49.66)
DS4: length 36.2
  TOP w0.635: LD4.A 28.51,16.1 ; LD4.A 27.26,16.99 28.17,17.91 28.8,17.91 ; LD4.A 27.26,13.84
  BOTTOM w0.508: 30.92,13.14 C29.2 ; 31.21,15.59 C10.2 ; C10.2 29.02,15.59 v1(28.8,15.8) 28.6,16 D6.C ; C10.2 30.18,16.95 ; 31.03,17.16 R6.2 30.02,18.03 29.74,17.75 ; D6.C 26.77,16 ; D6.C 27.72,16.8 ; D6.C 27.72,15.15 ; 27.65,14.31 C6.2 27.09,13.37 26.34,14.12
  BOTTOM w0.635: C22.P 30.42,5.59 ; C22.P 32.13,6.86 ; C22.P 30.42,7.54 ; 30.42,5.59 30.92,5.08 32.11,5.08 ; 30.42,5.59 30.42,3.11 ; 31.01,10.57 31.01,9.55 30.42,8.95 30.42,7.54 ; 32.21,8.18 31.05,8.18 30.42,7.54
  BOTTOM w0.762: C29.2 30.02,13.58 30.02,15.43 C10.2
  vias: v1(28.83,17.09) v1(28.8,14.48)
I2C0_SCL: length 59.2
  TOP w0.203: v1(33.15,73.41) 31.88,74.68 19.88,74.68 16.19,70.99 4.25,70.99 v1(2.16,68.9) ; v1(2.16,47.88) 3.05,46.99 3.94,46.99
  BOTTOM w0.203: v1(33.15,73.41) 33.06,73.41 32.29,74.18 32.29,75.1 P1.5 ; v1(2.16,68.9) v1(2.16,47.88)
I2C0_SDA: length 57.9
  TOP w0.203: v1(3.75,68.9) 5.36,70.51 16.25,70.51 20.04,74.3 31.24,74.3 v1(32.13,73.41) ; 3.94,45.72 3.05,45.72 v1(2.16,46.61)
  BOTTOM w0.203: P1.7 31.79,73.75 v1(32.13,73.41) ; v1(2.16,46.61) 2.92,47.37 2.92,68.07 v1(3.75,68.9)
INT_LASER: length 56.3
  TOP w0.203: v1(7.37,43.18) U6.5 ; R40.2 v1(8.76,48.01) ; v1(29.97,73.41) 29.21,72.64 27.97,72.64 27.65,72.96 22.03,72.96 20.45,71.37 19.02,71.37 18.16,70.52 18.16,69.47 18.61,69.02 18.61,65.6 14.35,61.34 8.13,61.34 v1(7.62,61.85)
  BOTTOM w0.203: v1(7.62,61.85) 8.25,61.21 8.25,60.33 7.49,59.56 7.49,53.47 8.76,52.2 v1(8.76,48.01) 8.76,44.58 v1(7.37,43.18) ; P1.13 30.29,73.72 v1(29.97,73.41)
IOVDD: length 48.7
  TOP w0.203: v1(4.65,66.65) 12.93,66.65 19.69,73.41 v1(28.7,73.41)
  TOP w0.254: v1(7.37,51.56) R41.1 R40.1
  BOTTOM w0.203: v1(4.65,66.65) 4.06,66.07 4.06,54.86 v1(7.37,51.56) ; v1(28.7,73.41) 29.07,73.41 29.79,74.12 P1.15
LD1: length 102.9
  TOP w0.305: v3(2.42,16.99) 1.52,16.99 1.07,17.45 1.07,36.88 1.8,37.62 5.08,37.62 5.84,38.38 5.84,52.07 5.42,52.5 2.29,52.5 1.98,52.8 1.98,53.41 2.29,53.71 5.54,53.71 5.84,54.02 5.84,54.63 5.54,54.93 2.29,54.93 1.98,55.24 1.98,55.85 2.29,56.15 5.59,56.15 5.89,56.46 5.89,57.07 5.59,57.37 2.29,57.37 1.98,57.68 1.98,58.29 2.29,58.59 4.8,58.59 5.11,58.9 5.11,59.51 4.8,59.81 2.29,59.81 1.98,60.12 1.98,60.73 2.29,61.03 4.83,61.03 5.13,61.33 5.13,61.94 4.83,62.25 2.29,62.25 1.98,62.55 1.98,63.16 2.29,63.47 3.52,63.47 3.94,63.88 3.94,64.52 5,65.58 15.49,65.58 16.8,66.89 v3(17.87,66.89)
  BOTTOM w0.305: v3(17.87,66.89) 18.78,67.8 P1.60 ; v3(2.42,16.99) 2.29,17.13 R1.1 2.42,17.91 U1.2
LD2: length 102.9
  TOP w0.305: v3(50.27,47.04) 50.27,48.29 49.96,48.59 49.11,48.59 48.81,48.29 48.81,47.22 48.5,46.91 47.89,46.91 47.59,47.22 47.59,48.29 47.28,48.59 46.67,48.59 46.37,48.29 46.37,47.22 46.06,46.91 45.45,46.91 45.15,47.22 45.15,48.29 44.85,48.59 44.12,48.59 43.81,48.9 43.81,49.5 44.12,49.81 50.39,49.81 50.7,50.11 50.7,50.72 50.39,51.03 44.48,51.03 44.17,51.33 44.17,51.94 44.48,52.25 50.29,52.25 50.6,52.55 50.6,53.16 50.29,53.47 45.52,53.47 45.21,53.77 45.21,54.38 45.52,54.69 50.29,54.69 50.6,54.99 50.6,55.6 50.29,55.91 45.52,55.91 45.21,56.21 45.21,56.82 45.52,57.12 50.34,57.12 50.65,57.43 50.65,57.94 50.34,58.24 45.52,58.24 45.21,58.55 45.21,59.41 46.28,60.48 46.28,62.03 45.67,62.64 36.04,62.64 31.98,66.7 24.84,66.7 24.44,67.1 23.62,67.1 23.47,66.95 21.66,66.95 v3(20.8,67.81)
  BOTTOM w0.305: P1.52 20.78,67.83 v3(20.8,67.81) ; U4.2 50.26,46 R10.1 50.27,46.25 v3(50.27,47.04)
LD3: length 102.9
  TOP w0.305: v3(28.29,62.81) 27.18,62.81 26.87,63.12 26.87,63.7 27.18,64.01 30.33,64.01 31.14,63.2 31.14,49.17 31.9,48.41 38.33,48.41 38.63,48.72 38.63,49.33 38.33,49.63 33.48,49.63 33.17,49.94 33.17,50.55 33.48,50.85 38.33,50.85 38.63,51.16 38.63,51.77 38.33,52.07 33.48,52.07 33.17,52.37 33.17,52.98 33.48,53.29 38.33,53.29 38.63,53.59 38.63,54.2 38.33,54.51 33.48,54.51 33.17,54.81 33.17,55.42 33.48,55.73 38.33,55.73 38.63,56.03 38.63,56.64 38.33,56.95 33.48,56.95 33.17,57.25 33.17,57.73 33.48,58.04 37.62,58.04 37.92,58.34 37.92,59.44 31.95,65.41 v3(24.03,65.41)
  BOTTOM w0.305: v3(24.03,65.41) 22.78,66.65 P1.44 ; U3.2 28.29,61.87 R9.1 28.29,62.14 v3(28.29,62.81)
LD4: length 102.9
  TOP w0.305: v1(42.42,38.73) 41.22,37.54 41.22,18.49 26.54,3.81 26.54,2.92 v3(25.53,1.91)
  BOTTOM w0.305: P1.36 24.79,70.02 25.83,71.07 33.01,71.07 34.12,69.95 42.32,69.95 48.42,63.85 48.42,57.05 47.94,56.58 47.94,54.47 48.18,54.23 48.18,48.87 42.42,43.1 v1(42.42,38.73) ; U2.2 24.61,2.11 R2.1 24.5,1.91 v3(25.53,1.91)
LD_SD1: length 73.9
  TOP w0.203: v2(10.46,71.7) 16,77.24 32.74,77.24 v2(33.78,76.2) 44.07,76.2 48.39,71.88 48.39,66.55 v2(45.47,63.63)
  BOTTOM w0.203: P3.1 12.32,62.26 11.46,63.12 11.46,65.05 9.35,67.16 9.35,70.59 v2(10.46,71.7) ; v2(33.78,76.2) 33.47,76.2 33.29,76.02 P1.1 ; P6.1 45.47,60.58 v2(45.47,63.63)
LD_SD2: length 81.6
  TOP w0.203: v2(47.5,59.23) 48.51,60.25 v2(48.51,65.41)
  BOTTOM w0.203: P4.1 9.14,61.44 8.28,62.31 8.28,67.41 8.61,67.74 8.61,71.32 14.66,77.37 31.7,77.37 32.79,76.28 ; 32.79,76.28 33.66,77.14 43.76,77.14 48.51,72.39 v2(48.51,65.41) ; 32.79,76.28 P1.3 ; P5.1 41.81,57.25 45.52,57.25 v2(47.5,59.23)
LD_SUPPLY: length 13.4
  BOTTOM w0.508: R5.1 v1(10.67,33.27) ; 16.84,63.32 R21.2 v1(18.19,63.32) ; v1(33.78,17.75) 33.01,17.75 R6.1 ; R11.1 v1(18.95,46.48)
  BOTTOM w0.635: v1(42.62,60.73) 42.62,62.05 R22.2 ; R22.2 42.62,62.26 v1(42.62,63.55) ; R22.2 43.21,61.67 43.68,61.67 v1(44.07,61.28) ; v1(16.84,64.85) v1(16.84,61.8) ; R13.1 v1(42.13,30.23)
SYNC: length 5.9
  TOP w0.203: U5.7 40.19,65.59 39.84,65.24 v2(39.41,65.24)
  BOTTOM w0.203: JP5.2 38.48,68.33 39.12,67.69 39.12,65.53 v2(39.41,65.24)
TAL1: length 72.2
  BOTTOM w0.305: P1.56 19.78,52.56 18.94,51.71 11.1,51.71 10.59,51.21 10.59,49.68 10.9,49.38 15.6,49.38 15.9,49.08 15.9,48.47 15.6,48.16 10.9,48.16 10.59,47.86 10.59,47.25 10.9,46.94 15.85,46.94 16.15,46.64 16.15,46.03 15.85,45.72 10.9,45.72 10.59,45.42 10.59,44.4 8.25,42.06 2.84,42.06 1.71,40.93 R25.2 1.57,33.98 R23.2
TAL2: length 72.2
  TOP w0.305: v3(43.03,35.33) 43.03,31.9 46.63,28.3 v3(50.29,28.3)
  BOTTOM w0.305: v3(50.29,28.3) 50.79,28.8 R26.2 50.79,31.29 R24.2 ; v3(43.03,35.33) 43.03,36.78 32.4,47.41 32.4,52.05 32.7,52.36 34.24,52.36 34.54,52.66 34.54,53.27 34.24,53.58 32.7,53.58 32.4,53.88 32.4,54.49 32.7,54.8 34.16,54.8 34.47,55.1 34.47,55.71 34.16,56.02 32.7,56.02 32.4,56.32 32.4,56.93 32.7,57.24 34.16,57.24 34.47,57.54 34.47,58.15 34.16,58.45 32.7,58.45 32.4,58.76 32.4,61.2 29.92,63.68 23.83,63.68 21.78,65.72 P1.48
TAL3: length 72.2
  TOP w0.305: v1(38.48,44.88) 37.59,45.77 31.12,45.77 v1(30.05,46.84)
  BOTTOM w0.305: P1.40 23.78,67.5 26.39,64.9 32.46,64.9 34.54,62.81 36.5,62.81 37.31,62 37.31,52.43 37.93,51.81 44.81,51.81 45.11,51.51 45.11,50.9 44.81,50.59 38.86,50.59 38.56,50.29 38.56,49.68 38.86,49.37 44.7,49.37 45.01,49.07 45.01,48.46 44.7,48.15 38.99,48.15 38.48,47.65 v1(38.48,44.88) ; v1(30.05,46.84) 30.05,47.68 R30.2 30.22,48.92 R28.2
TAL4: length 72.3
  TOP w0.305: v3(26.01,70.08) 24.89,68.96 20.65,68.96 19.94,68.25 19.94,48.64 12.01,40.72 12.01,24.82 20.93,15.9 v3(20.93,14.22)
  BOTTOM w0.305: v3(20.93,14.22) 21.66,14.22 R27.2 22.48,14.77 22.48,15.87 R29.2 ; v3(26.01,70.08) 25.79,69.86 P1.32
UNNAMED_4_ADP36X4_I6_INB: length 2.1
  BOTTOM w0.305: U1.4 1.12,17.95 R1.2
UNNAMED_4_ADP36X4_I6_OUTA: length 3
  BOTTOM w0.305: U1.7 2.42,26.42 R42.2 R7.1
UNNAMED_4_ADP36X4_I6_OUTB: length 2.6
  BOTTOM w0.305: U1.5 1.12,25.75 R42.1
UNNAMED_4_ADP36X4_I6_SD: length 46.2
  TOP w0.203: v2(3.24,18.57) 3.55,18.25 7.64,18.25 10.57,21.18 10.57,25.4 9.88,26.09 9.88,33.71 10.29,34.11 10.29,41.27 11.13,42.11 11.13,54.94 P3.2
  BOTTOM w0.203: v2(3.24,18.57) 3.07,18.74 U1.1
UNNAMED_4_ADP36X4_I6_VDD: length 6.1
  TOP w0.305: v3(1.77,25.31) 2.15,25.69 2.83,25.69 C1.2
  BOTTOM w0.305: U1.6 v3(1.77,25.31)
  BOTTOM w0.508: C3.2 5.3,22.07 v1(6.5,22.07) R31.2 7.54,22.21 v1(7.54,22.99)
UNNAMED_4_ADP36X4_I26_INB: length 2.1
  BOTTOM w0.305: R2.2 23.31,2.1 U2.4
UNNAMED_4_ADP36X4_I26_OUTA: length 3.1
  BOTTOM w0.305: U2.7 24.61,9.78 24.38,10.01 R44.2 24.38,11.28 R8.1
UNNAMED_4_ADP36X4_I26_OUTB: length 2.5
  BOTTOM w0.305: R44.1 23.31,10.18 U2.5
UNNAMED_4_ADP36X4_I26_SD: length 66.2
  TOP w0.203: P4.2 10.52,54.76 10.52,42.55 8.43,40.46 8.43,26.19 v2(9.73,24.89) ; v2(25.26,2.72) v2(22.05,5.92)
  BOTTOM w0.203: v2(22.05,5.92) 19.57,8.41 14.12,8.41 10.57,11.96 10.57,24.05 v2(9.73,24.89) ; U2.1 v2(25.26,2.72)
UNNAMED_4_ADP36X4_I26_VDD: length 7.2
  TOP w0.305: C2.2 24.1,9.75 v3(23.96,9.61)
  BOTTOM w0.305: U2.6 v3(23.96,9.61)
  BOTTOM w0.508: v1(21.67,3.17) 21.67,3.93 R33.2 21.67,4.2 v1(21.67,4.95) ; v1(27.58,7.37) C4.2 v1(26.3,6.24)
UNNAMED_4_ADP36X4_I59_INB: length 2
  BOTTOM w0.305: U3.4 29.59,61.83 R9.2
UNNAMED_4_ADP36X4_I59_OUTA: length 3.1
  BOTTOM w0.305: R12.1 28.5,52.73 R45.2 28.29,53.6 U3.7
UNNAMED_4_ADP36X4_I59_OUTB: length 2.5
  BOTTOM w0.305: R45.1 29.59,53.85 U3.5
UNNAMED_4_ADP36X4_I59_SD: length 35.9
  TOP w0.203: P5.2 41.58,54.94 41.58,48.69 39.7,46.81 31.72,46.81 29.85,48.69 29.85,55.12 27.58,57.38 v2(27.58,61.23)
  BOTTOM w0.305: v2(27.58,61.23) 27.64,61.17 U3.1
UNNAMED_4_ADP36X4_I59_VDD: length 7.5
  TOP w0.305: v3(28.94,54.41) 28.24,54.41 28.12,54.28 C7.2
  BOTTOM w0.305: U3.6 v3(28.94,54.41)
  BOTTOM w0.508: v1(27.03,61.75) R34.2 25.95,62.63 v1(26.09,62.76) ; v1(25.37,56.41) C11.2 v1(26.67,57.67)
UNNAMED_4_ADP36X4_I77_INB: length 2.2
  BOTTOM w0.305: R10.2 51.56,45.7 U4.4
UNNAMED_4_ADP36X4_I77_OUTA: length 3
  BOTTOM w0.305: R14.1 R43.2 50.37,38.05 50.26,38.15 U4.7
UNNAMED_4_ADP36X4_I77_OUTB: length 2.5
  BOTTOM w0.305: U4.5 51.56,38.05 R43.1
UNNAMED_4_ADP36X4_I77_SD: length 19.1
  TOP w0.203: v2(49.27,45.35) 49.26,45.35 49.02,45.59 43,45.59 42.29,46.3 42.29,54.86 P6.2
  BOTTOM w0.203: U4.1 49.61,45.01 v2(49.27,45.35)
UNNAMED_4_ADP36X4_I77_VDD: length 6
  TOP w0.305: C8.2 49.64,38.61 v3(50.9,38.61)
  BOTTOM w0.305: v3(50.9,38.61) 50.91,38.62 U4.6
  BOTTOM w0.508: v1(45.72,40.94) 45.58,41.08 R32.2 47.64,41.83 C12.2
UNNAMED_4_ADP250X_I213_EN: length 13.1
  TOP w0.203: U5.6 38.48,66.08 ; C25.1 40.51,64.89 40.51,65.28 40.69,65.46 U5.8
  TOP w0.508: 39.12,69.16 38.14,69.16 C24.2 37.94,68.97 R36.1 36.45,66.93 37.29,66.08 38.48,66.08 38.48,65.02 38.99,64.52 C25.1
UNNAMED_4_ADP250X_I213_FB: length 4.3
  TOP w0.203: U5.10 41.69,65.48 41.89,65.28 v2(41.91,65.28)
  BOTTOM w0.203: R35.2 R37.1 41.94,66.14 41.73,65.94 41.73,65.46 v2(41.91,65.28)
UNNAMED_4_ADP250X_I213_SW1: length 3.1
  TOP w0.254: U5.4 40.19,70.17 39.36,71.01 L1.1
UNNAMED_4_ADP250X_I213_SW2: length 3
  TOP w0.254: L1.2 41.77,70.98 41.19,70.4 U5.2
UNNAMED_4_ADP250X_I213_VOUT: length 8.4
  TOP w0.508: 42.19,69.14 43.42,69.14 C26.2 45.59,69.53 R39.1 45.63,66.91 v1(44.86,66.14)
  BOTTOM w0.508: R37.2 v1(44.86,66.14)
UNNAMED_4_CAP_I140_N2: length 7.9
  BOTTOM w0.381: C18.2 v1(35.31,65.81)
  BOTTOM w0.508: D8.C 33.26,65.87 33.43,66.04 v1(34.23,66.04) ; 39.83,62.15 v1(39.83,63.55) ; 39.83,62.15 R22.1 38.86,62.15 v1(38.48,61.77) ; 39.83,62.15 v1(39.83,60.81)
UNNAMED_4_DIOZNR_I124_P: length 9.3
  TOP w0.381: LD1.C 3.28,31.75 v2(3.28,29.69)
  BOTTOM w0.203: v2(3.28,29.69) 3.09,29.69 2.88,29.49 Q1.3 ; 3.68,29.44 Q1.5
  BOTTOM w0.254: v2(3.28,29.69) 3.43,29.69 3.68,29.44
  BOTTOM w0.305: R25.1 3.22,33.6 D5.A
  BOTTOM w0.381: D5.A 3.28,31.69 v2(3.28,29.69)
UNNAMED_4_DIOZNR_I125_P: length 8.5
  TOP w0.381: v2(25.6,13.87) 25.6,15.65 LD4.C
  BOTTOM w0.203: Q2.5 26.05,13.42 v2(25.6,13.87) 25.25,13.52 Q2.3
  BOTTOM w0.381: R29.1 D6.A 25.6,15.92 v2(25.6,13.87)
UNNAMED_4_DIOZNR_I126_P: length 9.4
  TOP w0.381: LD2.C 49.25,32.63 v2(49.25,34.24)
  BOTTOM w0.203: Q4.5 48.82,34.57 49.15,34.24 v2(49.25,34.24) 49.35,34.24 49.62,34.51 Q4.3
  BOTTOM w0.305: D10.A 49.79,31.78 R26.1
  BOTTOM w0.381: D10.A 49.25,32.32 v2(49.25,34.24)
UNNAMED_4_DIOZNR_I127_P: length 11.8
  TOP w0.305: v2(28.57,49.4) 27.56,49.4 27.26,49.1 LD3.C
  BOTTOM w0.203: Q3.5 26.75,50.21 27.56,49.4 v2(28.57,49.4) 28.57,49.86 28.35,50.09 27.81,50.09 27.55,50.35 Q3.3
  BOTTOM w0.305: R30.1 D9.A
  BOTTOM w0.381: v2(28.57,49.4) 28.57,49.1 28.19,48.72 27.81,48.72 27.19,48.09 D9.A
UNNAMED_4_RES_I11_N2: length 6.3
  BOTTOM w0.203: R7.2 2.48,27.8 Q1.1 ; R23.1 0.64,30.44 0.64,28.42 1.19,27.87 R17.1
  BOTTOM w0.305: R7.2 1.46,27.74 R17.1
UNNAMED_4_RES_I53_N2: length 5.4
  TOP w0.381: v2(2.34,29.68) 2.34,28.75 3.22,27.87 v2(3.28,27.87)
  BOTTOM w0.203: Q1.4 v2(3.28,27.87) ; Q1.2 2.48,29.43 2.48,29.44 2.48,29.54 v2(2.34,29.68)
  BOTTOM w0.508: v2(3.28,27.87) 3.28,27.17 R3.2
UNNAMED_4_RES_I54_N2: length 5.5
  TOP w0.381: v2(25.65,12.14) 24.94,12.14 24.41,12.67 v2(24.41,13.61)
  BOTTOM w0.203: v2(25.65,12.14) Q2.4 ; Q2.2 24.85,13.41 24.65,13.61 v2(24.41,13.61)
  BOTTOM w0.508: R4.2 25.65,12.14 v2(25.65,12.14)
UNNAMED_4_RES_I70_N2: length 4.6
  TOP w0.381: v2(27.15,51.82) 27.34,51.82 v2(28.46,50.7)
  BOTTOM w0.203: v2(27.15,51.82) 27.15,51.82 Q3.4 ; v2(28.46,50.7) Q3.2
  BOTTOM w0.508: R15.2 27.15,53.16 v2(27.15,51.82)
UNNAMED_4_RES_I87_N2: length 4.9
  TOP w0.381: v3(49.22,35.88) 49.22,35.58 50.33,34.47 v2(50.48,34.47)
  BOTTOM w0.203: v2(50.48,34.47) 50.29,34.47 50.02,34.74 Q4.2 ; Q4.4 v3(49.22,35.88)
  BOTTOM w0.381: v3(49.22,35.88) 48.97,36.12 48.97,37.23 R16.2
UNNAMED_4_RES_I116_N1: length 4.7
  BOTTOM w0.203: Q3.1 27.95,51.54 R12.2
  BOTTOM w0.305: R28.1 30.78,51.63 30.48,51.93 R19.1 29.37,52.08 R12.2
UNNAMED_4_RES_I118_N1: length 6.4
  BOTTOM w0.203: R14.2 50.22,36.23 50.02,36.03 Q4.1 ; R24.1 51.94,33.44 51.94,35.61 51.47,36.09 R20.1
  BOTTOM w0.381: R20.1 51.16,36.23 R14.2
UNNAMED_4_RES_I120_N1: length 4.5
  BOTTOM w0.203: Q2.1 24.85,12.38 R8.2
  BOTTOM w0.305: R8.2 23.41,11.93 R18.1 22.1,12.07 21.79,12.38 R27.1
VLD_BRD: length 18.6
  BOTTOM w0.305: P1.2 33.29,67.62 v1(33.32,67.59) ; v1(32.79,70.12) P1.4 32.79,67.61 32.77,67.59 ; 29.87,67.59 29.79,67.67 P1.16 ; P1.14 30.29,67.6 30.28,67.59 ; P1.8 31.79,67.85 v1(32.05,67.59) 32.29,67.83 P1.6 ; v1(30.78,67.59) 30.79,67.59 P1.12 ; v1(29.51,67.59) 29.29,67.82 P1.18 ; 31.29,67.59 31.29,67.59 P1.10 v1(31.29,70.12)
  BOTTOM w0.381: v1(29.51,67.59) v1(30.78,67.59) v1(32.05,67.59) v1(33.32,67.59)
VLD_EXT: length 9.6
  BOTTOM w0.508: P2.1 14.39,68.58 D7.C ; v1(10.62,64.01) C17.2 v1(9.52,62.36)
  BOTTOM w0.635: 14.05,63.32 v1(14.05,64.72) ; 14.05,63.32 v1(14.05,61.98) ; 14.05,63.32 R21.1 v1(12.55,63.32)

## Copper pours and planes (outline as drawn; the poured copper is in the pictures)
5V_LD on L3_PWR: 0.51,77.47 22.48,77.47 22.48,67.95 46.29,67.95 46.29,77.47 52.07,77.47 52.07,42.23 44.39,42.23 44.39,37.15 52.07,37.15 52.07,0.51 0.51,0.51 0.51,20.32 8.51,20.32 8.51,26.67 0.51,26.67 ; 2 cut-outs
5VDD_CON on L3_PWR: 23.11,68.58 23.11,77.47 45.66,77.47 45.66,68.58
AGND on BOTTOM: 8.89,40.77 8.89,34.67 9.4,34.16 10.59,34.16 13.46,37.03 13.46,40.77 12.62,41.61 9.73,41.61
AGND on BOTTOM: 39.45,26.26 39.45,21.06 40.08,20.42 43.26,20.42 44.02,21.18 44.02,27.66 43.26,28.42 41.61,28.42
AGND on BOTTOM: 18.29,60.45 15.11,60.45 13.97,59.31 13.97,52.83 14.35,52.45 18.03,52.45 18.67,53.09 18.67,60.07
AGND on BOTTOM: 34.04,10.41 34.04,2.92 34.42,2.54 38.23,2.54 38.73,3.05 38.73,10.54 38.23,11.05 34.67,11.05
AGND on L2_GND: 52.07,77.47 0.51,77.47 0.51,0.51 52.07,0.51
AGND on L5_GND: 52.07,77.47 0.51,77.47 0.51,0.51 52.07,0.51
(no net) on BOTTOM: 26.14,13.87 26.14,17.27 26.85,17.98 28.5,17.98 28.78,18.26 30.73,18.26 30.73,18.21 32,16.94 32,13.33 32.64,12.7 32.64,3.05 32.26,2.67 29.77,2.67 29.77,11.89 28.07,13.59 26.42,13.59 ; 1 cut-out
(no net) on L4_PWR: 15.49,60.96 6.6,60.96 6.6,71.12 15.49,71.12
3P3VDD on L4_PWR: 0.57,44.45 0.57,77.47 32,77.47 32,73.98 27.88,73.98 27.88,66.99 16.13,66.99 16.13,71.75 5.97,71.75 5.97,44.45
DS1 on TOP: 4.29,34.85 4.29,29.44 4.5,29.24 6.91,29.24 7.49,29.82 7.49,34.85
DS1 on BOTTOM: 6.22,28.58 4.19,28.58 4.19,38.23 7.49,38.23 7.49,35.36 8.48,34.37 8.48,32 9.6,30.89 9.6,27.36 9.3,27.05 7.75,27.05
DS2 on TOP: 45.8,34.85 48.49,34.85 48.49,29.24 46.71,29.24 45.8,30.15
DS2 on BOTTOM: 44.58,24.26 44.58,30.81 45.49,30.81 45.49,30.66 45.69,30.66 45.69,31.52 45.49,31.52 45.49,31.37 44.32,31.37 43.43,32.26 43.43,35.56 43.56,35.69 46.23,35.69 46.61,35.31 46.61,35.32 48.32,35.32 48.77,34.88 48.77,24.26
DS3 on TOP: 22.76,50.7 22.76,46.33 22.99,46.1 23.88,46.1 25.96,48.18 25.96,50.83 25.73,51.05 23.11,51.05
DS3 on BOTTOM: 21.33,47.2 21.33,46.1 26.11,46.1 26.11,50.67 25.86,50.93 24.38,50.93 23.37,51.94 22.35,51.94 21.84,52.45 21.84,53.72 21.72,53.85 20.45,53.85 20.32,53.72 20.32,48.21 ; 1 cut-out
DS4 on BOTTOM (solid shape): outline of 247 points within 26.14,2.67 32.64,18.26
DS4 on TOP: 26.39,16.94 26.39,13.74 26.85,13.28 29.21,13.28 29.67,13.74 29.67,17.81 29.18,18.29 27.74,18.29
LD_SUPPLY on L4_PWR: 0.51,43.81 0.51,0.51 52.07,0.51 52.07,64.13 42.16,64.13 42.16,59.69 32.96,59.69 32.96,66.36 16.13,66.36 16.13,60.33 6.6,60.33 6.6,43.81
UNNAMED_4_ADP36X4_I6_VDD on L3_PWR: 0.51,26.04 0.51,20.96 7.87,20.96 7.87,26.04
UNNAMED_4_ADP36X4_I26_VDD on L3_PWR: 21.21,2.51 21.21,10.16 28.19,10.16 28.19,2.51
UNNAMED_4_ADP36X4_I59_VDD on L3_PWR: 33.27,52.7 33.27,63.5 25.65,63.5 25.65,58.74 24.38,58.74 24.38,52.7
UNNAMED_4_ADP36X4_I77_VDD on L3_PWR: 45.02,41.59 45.02,37.72 52.07,37.72 52.07,41.59
UNNAMED_4_CAP_I140_N2 on L4_PWR: 33.59,66.36 33.59,60.33 41.53,60.33 41.53,64.77 52.07,64.77 52.07,71.75 38.67,71.75 38.67,66.36
VLD_BRD on L4_PWR: 52.07,77.47 52.07,72.39 38.04,72.39 38.04,66.99 28.51,66.99 28.51,73.34 32.64,73.34 32.64,77.47
VLD_EXT on L4_PWR (solid shape): 15.49,60.96 8.13,60.96 7.62,61.28 7.11,60.96 6.6,60.96 6.6,71.12 15.49,71.12

Small or netless copper shapes (teardrops, artwork), in the pictures only: 2 on TOP

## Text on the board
Ref Des/Assembly Bottom: A | C | 3 | 2 | 1 | 1. SHORT PINS 1 AND 2 OF JP5 USING SOLDER BLOB | ASSEMBLY NOTES:
Ref Des/Silkscreen Bottom: VLD_EXT | 08-051355 REV A | SECONDARY SIDE | LD_SUP | VLD_BRD
Ref Des/Assembly Top: C | A | 1
Ref Des/Silkscreen Top: C | LD_SD | A | GND | LD4 | PRIMARY SIDE | LD1 | 08-051355 REV A | VLD_EXT | 3D ToF LASER | LD3 | LD2 | 1 | 987126A
DIMENSION: REF | DIA MAX
PAGE_OUTLINE: 06NOV18 | CUSTOMER EVAL Z
DISPLAY_BOTTOM: 08-      -11
User.12: 15.    BOARDS TO BE SHIPPED IN ARRAYS
User.45: FIGURE | SIZE | 8.0 | 12.0 | 45.0 | 65.0 | 40.0 | 120.0 | PLATED | NON-PLATED | FINISHED HOLES IN MILS | ALL UNITS ARE IN MILS | QTY | 28 | 178 | 12 | 4 | 2 | 1 | TOLERANCE/NOTES
